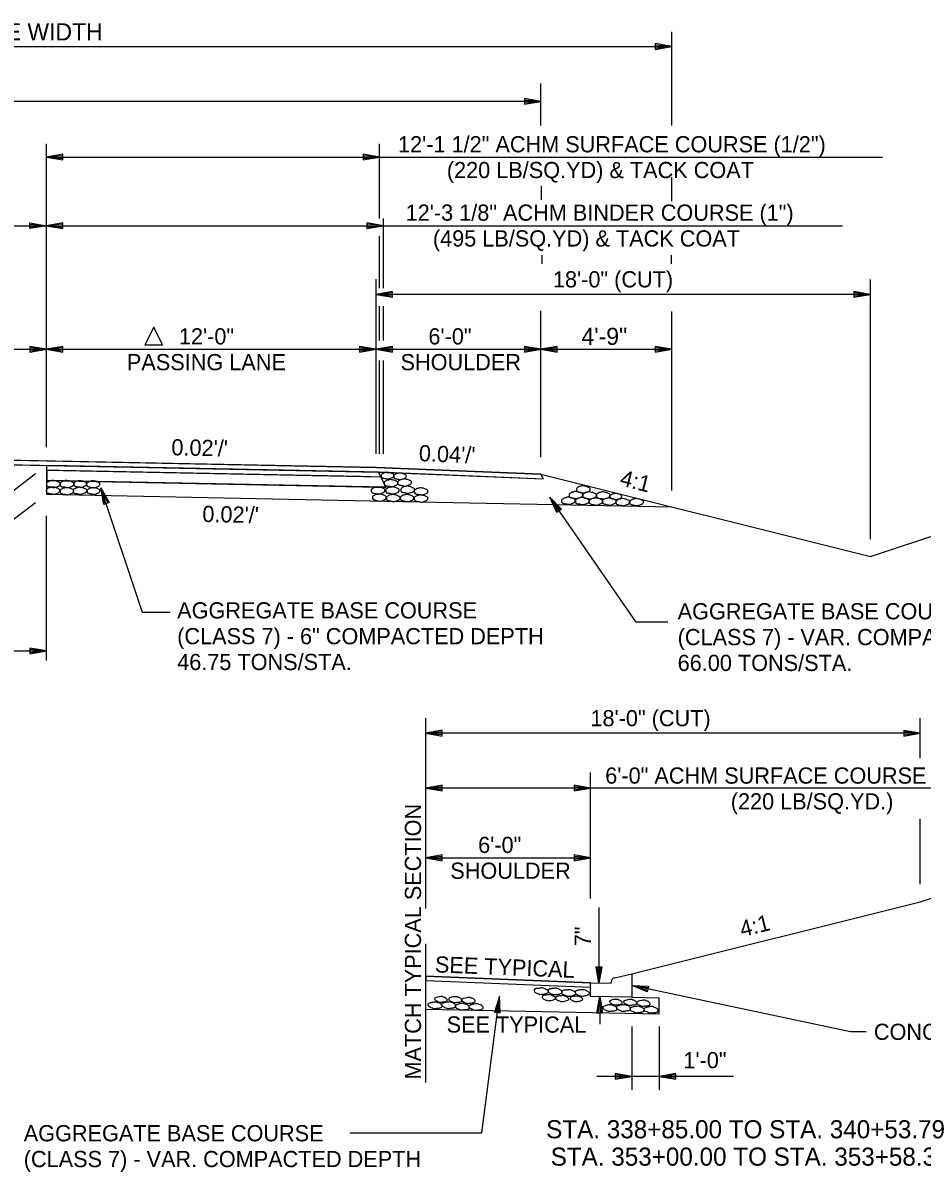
# Model space of a CAD drawing. Extents: x 1398183 to 1398373, y 1967240 to 1968889.
# Drawn here: x 1398256.3 to 1398289.03, y 1968479.69 to 1968521.54 of the extents above; entities that cross this region are included whole.
import ezdxf

# ---------------------------------------------------------------- set-up
doc = ezdxf.new("R2010")
doc.units = 0
for name, color, linetype in [('1', 7, 'Continuous'), ('10', 7, 'Continuous'), ('19', 7, 'Continuous'), ('42', 7, 'Continuous'), ('Level 1', 7, 'Continuous')]:
    doc.layers.add(name, color=color, linetype=linetype)

# ---------------------------------------------------------------- blocks, each defined once
blk = doc.blocks.new('ROCKS')
at = {"layer": '1'}
blk.add_spline([(0.013, 0.06), (0.053, 0.053), (0.107, 0.033), (0.133, 0.013), (0.133, -0.007), (0.12, -0.033), (0.107, -0.04), (0.073, -0.053), (0.033, -0.067), (0.013, -0.067), (-0.02, -0.06), (-0.06, -0.053), (-0.087, -0.047), (-0.113, -0.02), (-0.113, -0.007), (-0.107, 0.02), (-0.087, 0.033), (-0.067, 0.047), (-0.033, 0.053), (-0.02, 0.06), (0.013, 0.06)], degree=3, dxfattribs=at)

msp = doc.modelspace()

# ---------------------------------------------------------------- linework, layer by layer
at = {"layer": '10'}
msp.add_lwpolyline([(1398261.055, 1968510.466), (1398260.735, 1968509.824), (1398261.376, 1968509.824)], close=True, dxfattribs=at)
at = {"layer": '19'}
for p, q in [((1398279.917, 1968517.807), (1398279.917, 1968521.226)), ((1398222.545, 1968520.685), (1398279.917, 1968520.685)), ((1398279.317, 1968520.79), (1398279.317, 1968520.58)), ((1398279.917, 1968520.685), (1398279.317, 1968520.79)), ((1398279.757, 1968520.7), (1398279.317, 1968520.735)), ((1398279.317, 1968520.58), (1398279.917, 1968520.685)), ((1398279.317, 1968520.63), (1398279.757, 1968520.67)), ((1398275.152, 1968517.807), (1398275.152, 1968519.333)), ((1398275.152, 1968518.685), (1398225.119, 1968518.685)), ((1398274.552, 1968518.79), (1398274.552, 1968518.58)), ((1398275.152, 1968518.685), (1398274.552, 1968518.79)), ((1398274.992, 1968518.7), (1398274.552, 1968518.735)), ((1398274.552, 1968518.58), (1398275.152, 1968518.685)), ((1398274.552, 1968518.63), (1398274.992, 1968518.67)), ((1398257.15, 1968506.092), (1398257.15, 1968517.142)), ((1398269.279, 1968514.427), (1398269.279, 1968517.142)), ((1398257.75, 1968516.765), (1398257.15, 1968516.66)), ((1398257.15, 1968516.66), (1398257.75, 1968516.555)), ((1398257.15, 1968516.66), (1398287.584, 1968516.66)), ((1398257.75, 1968516.71), (1398257.31, 1968516.675)), ((1398257.31, 1968516.645), (1398257.75, 1968516.605)), ((1398257.75, 1968516.555), (1398257.75, 1968516.765)), ((1398268.679, 1968516.765), (1398268.679, 1968516.555)), ((1398269.279, 1968516.66), (1398268.679, 1968516.765)), ((1398269.119, 1968516.675), (1398268.679, 1968516.71)), ((1398268.679, 1968516.555), (1398269.279, 1968516.66)), ((1398268.679, 1968516.605), (1398269.119, 1968516.645)), ((1398279.911, 1968515.927), (1398279.911, 1968515.052)), ((1398275.17, 1968515.104), (1398275.17, 1968515.613)), ((1398269.417, 1968511.884), (1398269.417, 1968514.425)), ((1398233.15, 1968514.16), (1398286.13, 1968514.16)), ((1398256.55, 1968514.055), (1398256.55, 1968514.265)), ((1398256.55, 1968514.265), (1398257.15, 1968514.16)), ((1398256.55, 1968514.21), (1398256.99, 1968514.175)), ((1398257.15, 1968514.16), (1398256.55, 1968514.055)), ((1398256.99, 1968514.145), (1398256.55, 1968514.105)), ((1398257.75, 1968514.265), (1398257.15, 1968514.16)), ((1398257.15, 1968514.16), (1398257.75, 1968514.055)), ((1398257.75, 1968514.21), (1398257.31, 1968514.175)), ((1398257.31, 1968514.145), (1398257.75, 1968514.105)), ((1398257.75, 1968514.055), (1398257.75, 1968514.265)), ((1398268.817, 1968514.265), (1398268.817, 1968514.055)), ((1398269.417, 1968514.16), (1398268.817, 1968514.265)), ((1398269.257, 1968514.175), (1398268.817, 1968514.21)), ((1398268.817, 1968514.055), (1398269.417, 1968514.16)), ((1398268.817, 1968514.105), (1398269.257, 1968514.145)), ((1398269.279, 1968511.884), (1398269.279, 1968513.784)), ((1398275.204, 1968512.767), (1398275.204, 1968513.089)), ((1398279.911, 1968512.767), (1398279.911, 1968513.089)), ((1398269.15, 1968505.852), (1398269.15, 1968512.207)), ((1398287.15, 1968502.738), (1398287.15, 1968512.206)), ((1398269.75, 1968511.765), (1398269.15, 1968511.66)), ((1398285.15, 1968511.66), (1398269.15, 1968511.66)), ((1398269.15, 1968511.66), (1398269.75, 1968511.555)), ((1398287.15, 1968511.66), (1398269.15, 1968511.66)), ((1398269.75, 1968511.71), (1398269.31, 1968511.675)), ((1398269.31, 1968511.645), (1398269.75, 1968511.605)), ((1398269.75, 1968511.555), (1398269.75, 1968511.765)), ((1398286.55, 1968511.765), (1398286.55, 1968511.555)), ((1398287.15, 1968511.66), (1398286.55, 1968511.765)), ((1398286.99, 1968511.675), (1398286.55, 1968511.71)), ((1398286.55, 1968511.555), (1398287.15, 1968511.66)), ((1398286.55, 1968511.605), (1398286.99, 1968511.645)), ((1398269.279, 1968509.983), (1398269.279, 1968511.232)), ((1398269.417, 1968509.981), (1398269.417, 1968511.23)), ((1398275.15, 1968505.732), (1398275.15, 1968511.056)), ((1398279.916, 1968504.514), (1398279.916, 1968511.037)), ((1398256.55, 1968509.765), (1398256.55, 1968509.555)), ((1398257.15, 1968509.66), (1398256.55, 1968509.765)), ((1398257.75, 1968509.765), (1398257.15, 1968509.66)), ((1398257.75, 1968509.555), (1398257.75, 1968509.765)), ((1398268.55, 1968509.765), (1398268.55, 1968509.555)), ((1398269.15, 1968509.66), (1398268.55, 1968509.765)), ((1398269.75, 1968509.765), (1398269.15, 1968509.66)), ((1398269.75, 1968509.555), (1398269.75, 1968509.765)), ((1398274.55, 1968509.765), (1398274.55, 1968509.555)), ((1398275.15, 1968509.66), (1398274.55, 1968509.765)), ((1398275.75, 1968509.765), (1398275.15, 1968509.66)), ((1398275.75, 1968509.555), (1398275.75, 1968509.765)), ((1398279.317, 1968509.765), (1398279.317, 1968509.555)), ((1398279.917, 1968509.66), (1398279.317, 1968509.765)), ((1398245.15, 1968509.66), (1398257.15, 1968509.66)), ((1398256.99, 1968509.675), (1398256.55, 1968509.71)), ((1398256.55, 1968509.555), (1398257.15, 1968509.66)), ((1398256.55, 1968509.605), (1398256.99, 1968509.645)), ((1398257.15, 1968509.66), (1398257.75, 1968509.555)), ((1398257.15, 1968509.66), (1398269.15, 1968509.66)), ((1398257.75, 1968509.71), (1398257.31, 1968509.675)), ((1398257.31, 1968509.645), (1398257.75, 1968509.605)), ((1398268.99, 1968509.675), (1398268.55, 1968509.71)), ((1398268.55, 1968509.555), (1398269.15, 1968509.66)), ((1398268.55, 1968509.605), (1398268.99, 1968509.645)), ((1398269.15, 1968509.66), (1398275.15, 1968509.66)), ((1398269.15, 1968509.66), (1398269.75, 1968509.555)), ((1398269.75, 1968509.71), (1398269.31, 1968509.675)), ((1398269.31, 1968509.645), (1398269.75, 1968509.605)), ((1398274.99, 1968509.675), (1398274.55, 1968509.71)), ((1398274.55, 1968509.555), (1398275.15, 1968509.66)), ((1398274.55, 1968509.605), (1398274.99, 1968509.645)), ((1398275.15, 1968509.66), (1398279.916, 1968509.66)), ((1398275.15, 1968509.66), (1398275.75, 1968509.555)), ((1398275.75, 1968509.71), (1398275.31, 1968509.675)), ((1398275.31, 1968509.645), (1398275.75, 1968509.605)), ((1398279.757, 1968509.675), (1398279.317, 1968509.71)), ((1398279.317, 1968509.555), (1398279.917, 1968509.66)), ((1398279.317, 1968509.605), (1398279.757, 1968509.645)), ((1398269.279, 1968505.852), (1398269.279, 1968509.252)), ((1398269.417, 1968505.852), (1398269.417, 1968509.249)), ((1398257.15, 1968505.425), (1398257.15, 1968505.258)), ((1398257.15, 1968505.258), (1398257.15, 1968504.883)), ((1398257.15, 1968505.258), (1398269.322, 1968505.012)), ((1398268.585, 1968505.024), (1398257.611, 1968505.243)), ((1398269.237, 1968505.182), (1398269.322, 1968505.012)), ((1398287.15, 1968502.113), (1398296.517, 1968505.235)), ((1398256.753, 1968505.121), (1398254.051, 1968503.052)), ((1398257.15, 1968504.883), (1398257.15, 1968504.383)), ((1398269.511, 1968504.633), (1398257.15, 1968504.883)), ((1398269.328, 1968505.007), (1398268.585, 1968505.024)), ((1398269.322, 1968505.012), (1398269.511, 1968504.633)), ((1398269.518, 1968504.628), (1398269.328, 1968505.007)), ((1398275.15, 1968505.112), (1398287.15, 1968502.113)), ((1398275.15, 1968505.112), (1398275.235, 1968504.942)), ((1398259.233, 1968504.011), (1398259.132, 1968504.61)), ((1398259.132, 1968504.61), (1398259.43, 1968504.079)), ((1398260.643, 1968500.074), (1398259.133, 1968504.607)), ((1398259.28, 1968504.028), (1398259.17, 1968504.454)), ((1398259.196, 1968504.464), (1398259.379, 1968504.064)), ((1398268.662, 1968504.646), (1398269.518, 1968504.628)), ((1398256.747, 1968504.072), (1398254.065, 1968502.02)), ((1398259.43, 1968504.079), (1398259.233, 1968504.011)), ((1398278.623, 1968499.715), (1398275.478, 1968504.267)), ((1398275.731, 1968503.714), (1398275.478, 1968504.267)), ((1398275.478, 1968504.267), (1398275.904, 1968503.831)), ((1398275.771, 1968503.743), (1398275.555, 1968504.126)), ((1398275.578, 1968504.143), (1398275.858, 1968503.804)), ((1398257.15, 1968498.324), (1398257.15, 1968503.592)), ((1398275.904, 1968503.831), (1398275.731, 1968503.714)), ((1398261.656, 1968500.074), (1398260.643, 1968500.074)), ((1398279.774, 1968499.715), (1398278.623, 1968499.715)), ((1398233.15, 1968498.674), (1398257.15, 1968498.674)), ((1398256.55, 1968498.779), (1398256.55, 1968498.569)), ((1398257.15, 1968498.674), (1398256.55, 1968498.779)), ((1398256.99, 1968498.689), (1398256.55, 1968498.724)), ((1398256.55, 1968498.569), (1398257.15, 1968498.674)), ((1398256.55, 1968498.619), (1398256.99, 1968498.659)), ((1398270.961, 1968489.287), (1398270.961, 1968496.224)), ((1398288.961, 1968494.765), (1398288.961, 1968496.222)), ((1398271.561, 1968495.783), (1398270.961, 1968495.678)), ((1398288.961, 1968495.678), (1398270.961, 1968495.678)), ((1398270.961, 1968495.678), (1398271.561, 1968495.573)), ((1398271.561, 1968495.728), (1398271.121, 1968495.693)), ((1398271.121, 1968495.663), (1398271.561, 1968495.623)), ((1398271.561, 1968495.573), (1398271.561, 1968495.783)), ((1398288.361, 1968495.78), (1398288.361, 1968495.57)), ((1398288.961, 1968495.675), (1398288.361, 1968495.78)), ((1398288.801, 1968495.69), (1398288.361, 1968495.725)), ((1398288.361, 1968495.57), (1398288.961, 1968495.675)), ((1398288.361, 1968495.62), (1398288.801, 1968495.66)), ((1398276.961, 1968489.65), (1398276.961, 1968494.245)), ((1398271.561, 1968493.783), (1398270.961, 1968493.678)), ((1398294.328, 1968493.678), (1398270.961, 1968493.678)), ((1398270.961, 1968493.678), (1398271.561, 1968493.573)), ((1398271.561, 1968493.728), (1398271.121, 1968493.693)), ((1398271.121, 1968493.663), (1398271.561, 1968493.623)), ((1398271.561, 1968493.573), (1398271.561, 1968493.783)), ((1398276.361, 1968493.783), (1398276.361, 1968493.573)), ((1398276.961, 1968493.678), (1398276.361, 1968493.783)), ((1398276.801, 1968493.693), (1398276.361, 1968493.728)), ((1398276.361, 1968493.573), (1398276.961, 1968493.678)), ((1398276.361, 1968493.623), (1398276.801, 1968493.663)), ((1398288.961, 1968490.172), (1398288.961, 1968492.562)), ((1398288.961, 1968489.534), (1398294.559, 1968491.4)), ((1398271.561, 1968491.243), (1398270.961, 1968491.138)), ((1398270.961, 1968491.138), (1398276.961, 1968491.138)), ((1398270.961, 1968491.138), (1398271.561, 1968491.033)), ((1398271.561, 1968491.188), (1398271.121, 1968491.153)), ((1398271.121, 1968491.123), (1398271.561, 1968491.083)), ((1398271.561, 1968491.033), (1398271.561, 1968491.243)), ((1398276.361, 1968491.243), (1398276.361, 1968491.033)), ((1398276.961, 1968491.138), (1398276.361, 1968491.243)), ((1398276.801, 1968491.153), (1398276.361, 1968491.188)), ((1398276.361, 1968491.033), (1398276.961, 1968491.138)), ((1398276.361, 1968491.083), (1398276.801, 1968491.123)), ((1398277.266, 1968489.332), (1398277.266, 1968486.567)), ((1398278.461, 1968486.909), (1398288.961, 1968489.534)), ((1398270.961, 1968482.949), (1398270.961, 1968488.001)), ((1398277.161, 1968487.167), (1398277.371, 1968487.167)), ((1398277.266, 1968486.567), (1398277.161, 1968487.167)), ((1398277.251, 1968486.727), (1398277.211, 1968487.167)), ((1398277.371, 1968487.167), (1398277.266, 1968486.567)), ((1398277.316, 1968487.167), (1398277.281, 1968486.727)), ((1398277.841, 1968486.771), (1398278.461, 1968486.909)), ((1398278.461, 1968486.909), (1398278.461, 1968486.06)), ((1398276.961, 1968486.09), (1398276.961, 1968486.59)), ((1398276.961, 1968486.59), (1398277.711, 1968486.575)), ((1398277.711, 1968486.575), (1398277.711, 1968486.608)), ((1398286.421, 1968484.8), (1398278.461, 1968486.484)), ((1398279.025, 1968486.259), (1398278.461, 1968486.484)), ((1398278.461, 1968486.484), (1398279.069, 1968486.462)), ((1398279.034, 1968486.307), (1398278.613, 1968486.436)), ((1398278.619, 1968486.463), (1398279.055, 1968486.411)), ((1398279.069, 1968486.462), (1398279.025, 1968486.259)), ((1398273.006, 1968481.116), (1398273.643, 1968486.102)), ((1398273.643, 1968486.102), (1398273.464, 1968485.52)), ((1398273.611, 1968485.945), (1398273.517, 1968485.516)), ((1398273.622, 1968485.501), (1398273.639, 1968485.942)), ((1398273.671, 1968485.495), (1398273.643, 1968486.102)), ((1398278.461, 1968486.06), (1398276.961, 1968486.09)), ((1398277.189, 1968485.484), (1398277.294, 1968486.084)), ((1398277.239, 1968485.484), (1398277.279, 1968485.924)), ((1398277.294, 1968486.084), (1398277.399, 1968485.484)), ((1398277.294, 1968486.084), (1398277.294, 1968485.084)), ((1398277.309, 1968485.924), (1398277.344, 1968485.484)), ((1398279.461, 1968485.452), (1398279.461, 1968486.04)), ((1398273.464, 1968485.52), (1398273.671, 1968485.495)), ((1398277.399, 1968485.484), (1398277.189, 1968485.484)), ((1398278.461, 1968484.988), (1398278.461, 1968482.686)), ((1398279.461, 1968484.988), (1398279.461, 1968482.686)), ((1398286.991, 1968484.8), (1398286.421, 1968484.8)), ((1398282.166, 1968483.178), (1398277.185, 1968483.178)), ((1398277.861, 1968483.283), (1398277.861, 1968483.073)), ((1398278.461, 1968483.178), (1398277.861, 1968483.283)), ((1398278.301, 1968483.193), (1398277.861, 1968483.228)), ((1398277.861, 1968483.073), (1398278.461, 1968483.178)), ((1398277.861, 1968483.123), (1398278.301, 1968483.163)), ((1398280.061, 1968483.283), (1398279.461, 1968483.178)), ((1398279.461, 1968483.178), (1398280.061, 1968483.073)), ((1398280.061, 1968483.228), (1398279.621, 1968483.193)), ((1398279.621, 1968483.163), (1398280.061, 1968483.123)), ((1398280.061, 1968483.073), (1398280.061, 1968483.283)), ((1398268.208, 1968481.116), (1398273.006, 1968481.116))]:
    msp.add_line(p, q, dxfattribs=at)
for points in [[(1398225.065, 1968505.102), (1398233.065, 1968505.422), (1398245.15, 1968505.666), (1398269.252, 1968505.191), (1398275.237, 1968504.942), (1398275.15, 1968505.112), (1398269.152, 1968505.352), (1398245.15, 1968505.832), (1398233.15, 1968505.592), (1398225.15, 1968505.272)], [(1398257.15, 1968505.425), (1398257.15, 1968505.258), (1398257.959, 1968505.242), (1398266.824, 1968505.062), (1398269.321, 1968505.011), (1398269.236, 1968505.181), (1398268.177, 1968505.203), (1398257.894, 1968505.41)], [(1398270.961, 1968486.664), (1398276.961, 1968486.424), (1398276.961, 1968486.59), (1398270.961, 1968486.83)]]:
    msp.add_lwpolyline(points, close=True, dxfattribs=at)
for points in [[(1398225.065, 1968505.102), (1398233.065, 1968505.422), (1398245.15, 1968505.666), (1398269.237, 1968505.182), (1398275.235, 1968504.942)], [(1398245.15, 1968505.832), (1398257.15, 1968505.592), (1398269.15, 1968505.352), (1398275.15, 1968505.112)], [(1398257.611, 1968505.243), (1398257.158, 1968505.254), (1398257.158, 1968504.879)], [(1398257.158, 1968504.879), (1398257.738, 1968504.865), (1398268.662, 1968504.646)], [(1398257.15, 1968504.383), (1398269.511, 1968504.133), (1398279.907, 1968503.923)], [(1398270.961, 1968486.83), (1398276.961, 1968486.59)], [(1398270.961, 1968486.664), (1398276.961, 1968486.424)], [(1398278.461, 1968486.06), (1398279.461, 1968486.04)], [(1398270.961, 1968485.622), (1398279.461, 1968485.452)]]:
    msp.add_lwpolyline(points, dxfattribs=at)
msp.add_arc((1398277.877, 1968486.608), 0.167, 102.5288, 180, dxfattribs=at)
at = {"layer": '42'}
msp.add_lwpolyline([(1398245.15, 1968505.666), (1398257.15, 1968505.425)], dxfattribs=at)

# ---------------------------------------------------------------- block references
at = {"layer": 'Level 1'}
for p, xscale, yscale, rotation in [((1398269.549, 1968505.062), 1.8771740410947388, 1.8771740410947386, -0.173618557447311), ((1398270.006, 1968505.037), 1.849824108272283, 1.8498241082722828, -0.17361855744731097), ((1398257.376, 1968504.758), 2.011654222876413, 2.0116542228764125, -0.17361855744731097), ((1398257.875, 1968504.756), 2.011654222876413, 2.0116542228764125, -0.17361855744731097), ((1398258.357, 1968504.759), 1.907051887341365, 1.9070518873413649, -0.173618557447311), ((1398258.833, 1968504.747), 1.9598639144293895, 1.959863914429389, -0.173618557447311), ((1398269.67, 1968504.788), 2.011654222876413, 2.0116542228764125, -0.17361855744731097), ((1398270.169, 1968504.813), 2.011654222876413, 2.0116542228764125, -0.17361855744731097), ((1398257.368, 1968504.517), 2.011654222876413, 2.0116542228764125, -0.17361855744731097), ((1398257.872, 1968504.498), 2.011654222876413, 2.0116542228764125, -0.17361855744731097), ((1398258.347, 1968504.512), 1.9974694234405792, 1.9974694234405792, -0.17361855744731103), ((1398258.844, 1968504.503), 1.890205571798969, 1.8902055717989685, -0.17361855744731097), ((1398269.2, 1968504.522), 2.011654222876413, 2.0116542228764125, -0.17361855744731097), ((1398269.251, 1968504.264), 2.011654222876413, 2.0116542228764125, -0.17361855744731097), ((1398269.724, 1968504.527), 2.011654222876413, 2.0116542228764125, -0.17361855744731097), ((1398269.755, 1968504.246), 2.011654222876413, 2.0116542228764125, -0.17361855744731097), ((1398270.26, 1968504.249), 2.011654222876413, 2.0116542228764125, -0.17361855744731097), ((1398270.279, 1968504.55), 2.011654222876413, 2.0116542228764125, -0.17361855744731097), ((1398270.764, 1968504.231), 2.011654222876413, 2.0116542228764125, -0.17361855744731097), ((1398270.768, 1968504.489), 2.011654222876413, 2.0116542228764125, -0.17361855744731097), ((1398276.404, 1968504.354), 2.011654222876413, 2.0116542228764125, -0.17361855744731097), ((1398276.673, 1968504.562), 2.011654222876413, 2.0116542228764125, -0.17361855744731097), ((1398276.904, 1968504.342), 2.011654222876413, 2.0116542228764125, -0.17361855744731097), ((1398277.399, 1968504.342), 2.011654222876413, 2.0116542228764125, -0.17361855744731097), ((1398277.861, 1968504.303), 1.7335100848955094, 1.7335100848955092, -0.173618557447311), ((1398276.133, 1968504.147), 2.011654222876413, 2.0116542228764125, -0.17361855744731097), ((1398276.133, 1968504.147), 2.011654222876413, 2.0116542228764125, -0.17361855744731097), ((1398276.638, 1968504.137), 2.011654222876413, 2.0116542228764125, -0.17361855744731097), ((1398276.638, 1968504.137), 2.011654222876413, 2.0116542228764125, -0.17361855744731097), ((1398277.13, 1968504.119), 2.011654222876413, 2.0116542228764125, -0.17361855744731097), ((1398277.13, 1968504.119), 2.011654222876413, 2.0116542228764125, -0.17361855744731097), ((1398277.62, 1968504.119), 2.011654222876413, 2.0116542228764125, -0.17361855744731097), ((1398277.62, 1968504.119), 2.011654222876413, 2.0116542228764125, -0.17361855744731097), ((1398278.113, 1968504.099), 2.011654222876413, 2.0116542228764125, -0.17361855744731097), ((1398278.113, 1968504.099), 2.011654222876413, 2.0116542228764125, -0.17361855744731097), ((1398278.616, 1968504.099), 2.011654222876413, 2.0116542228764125, -0.17361855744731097), ((1398278.616, 1968504.099), 2.011654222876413, 2.0116542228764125, -0.17361855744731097), ((1398275.145, 1968486.277), 2.0116542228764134, -2.011654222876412, -4.336484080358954), ((1398275.65, 1968486.266), 2.0116542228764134, -2.011654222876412, -4.336484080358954), ((1398276.144, 1968486.211), 2.0116542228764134, -2.011654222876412, -4.336484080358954), ((1398276.642, 1968486.214), 2.0116542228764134, -2.011654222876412, -4.336484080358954), ((1398271.317, 1968485.771), 2.0116542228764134, -2.011654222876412, 175.66351591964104), ((1398271.531, 1968485.985), 1.773922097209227, -1.7739220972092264, 175.66351591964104), ((1398271.815, 1968485.774), 2.0116542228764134, -2.011654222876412, 175.66351591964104), ((1398272.053, 1968485.977), 1.851115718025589, -1.8511157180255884, 175.66351591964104), ((1398272.535, 1968485.947), 1.8866375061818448, -1.886637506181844, 175.66351591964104), ((1398275.424, 1968486.038), 1.8866375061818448, -1.886637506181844, -4.336484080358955), ((1398275.906, 1968486.008), 1.851115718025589, -1.8511157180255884, -4.336484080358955), ((1398276.427, 1968486), 1.773922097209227, -1.7739220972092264, -4.336484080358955), ((1398277.899, 1968485.884), 1.773922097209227, -1.7739220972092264, 175.66351591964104), ((1398278.421, 1968485.877), 1.851115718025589, -1.8511157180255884, 175.66351591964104), ((1398278.903, 1968485.846), 1.8866375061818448, -1.886637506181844, 175.66351591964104), ((1398272.309, 1968485.719), 2.0116542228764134, -2.011654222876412, 175.66351591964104), ((1398272.814, 1968485.708), 2.0116542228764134, -2.011654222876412, 175.66351591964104), ((1398277.685, 1968485.67), 2.0116542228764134, -2.011654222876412, 175.66351591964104), ((1398278.182, 1968485.674), 2.0116542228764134, -2.011654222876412, 175.66351591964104), ((1398278.677, 1968485.618), 2.0116542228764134, -2.011654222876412, 175.66351591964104), ((1398279.182, 1968485.607), 2.0116542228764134, -2.011654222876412, 175.66351591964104)]:
    msp.add_blockref('ROCKS', p, dxfattribs=dict(at, xscale=xscale, yscale=yscale, rotation=rotation))

# ---------------------------------------------------------------- texts
at = {"layer": '10'}
for s, height, p in [('18\'-0" (CUT)', 0.59001, (1398275.59, 1968511.912)), ('12\'-0"', 0.59, (1398261.972, 1968509.835)), ('6\'-0"', 0.59, (1398271.056, 1968509.835)), ('PASSING LANE', 0.59001, (1398260.079, 1968508.895)), ('SHOULDER', 0.59, (1398270.043, 1968508.895)), ('18\'-0" (CUT)', 0.59001, (1398276.956, 1968495.929)), ('6\'-0" ACHM SURFACE COURSE (1/2")', 0.59001, (1398277.494, 1968493.839)), ('(220 LB/SQ.YD.)', 0.59001, (1398282.065, 1968492.899)), ('6\'-0"', 0.59, (1398272.867, 1968491.313)), ('SHOULDER', 0.59, (1398271.854, 1968490.373)), ('1\'-0"', 0.59, (1398280.34, 1968483.473))]:
    msp.add_text(s, height=height, dxfattribs=at).set_placement(p)
for s, height, rotation, p in [("0.04'/'", 0.59, 357.7094, (1398270.7, 1968505.586)), ('4:1', 0.59, 345.9638, (1398277.997, 1968504.705)), ('MATCH TYPICAL SECTION', 0.59001, 90, (1398270.789, 1968483.062)), ('4:1', 0.59, 14.0362, (1398282.479, 1968488.245)), ('SEE TYPICAL', 0.59001, 357.7094, (1398271.285, 1968486.967)), ('SEE TYPICAL', 0.59001, 359.948, (1398271.719, 1968484.773))]:
    msp.add_text(s, height=height, rotation=rotation, dxfattribs=at).set_placement(p)
at = {"layer": '19'}
for s, height, p in [('57\'-3" SUBGRADE WIDTH', 0.625, (1398249.173, 1968520.909)), ('4\'-9"', 0.625, (1398276.63, 1968509.818)), ('CONC. COMB. C&G (TYPE B-1) (1\'-6")', 0.59001, (1398287.276, 1968484.505)), ('STA. 338+85.00 TO STA. 340+53.79', 0.65999, (1398275.344, 1968480.922)), ('STA. 353+00.00 TO STA. 353+58.31', 0.65999, (1398275.508, 1968479.925))]:
    msp.add_text(s, height=height, dxfattribs=at).set_placement(p)
for s, height, rotation, p in [("0.02'/'", 0.59, 358.7305, (1398261.694, 1968505.8)), ("0.02'/'", 0.59, 358.7305, (1398262.821, 1968503.372)), ('AGGREGATE BASE COURSE', 0.59001, 360, (1398261.91, 1968499.855)), ('AGGREGATE BASE COURSE', 0.59001, 360, (1398280.132, 1968499.822)), ('(CLASS 7) - 6" COMPACTED DEPTH', 0.59001, 360, (1398261.91, 1968498.915)), ('(CLASS 7) - VAR. COMPACTED DEPTH', 0.59001, 360, (1398280.132, 1968498.882)), ('46.75 TONS/STA.', 0.59001, 360, (1398261.91, 1968497.975)), ('66.00 TONS/STA.', 0.59001, 360, (1398280.132, 1968497.942)), ('AGGREGATE BASE COURSE', 0.59001, 360, (1398256.323, 1968480.812)), ('(CLASS 7) - VAR. COMPACTED DEPTH', 0.59001, 360, (1398256.323, 1968479.872))]:
    msp.add_text(s, height=height, rotation=rotation, dxfattribs=at).set_placement(p)
at = {"layer": '42'}
for s, height, rotation, p in [('12\'-1 1/2" ACHM SURFACE COURSE (1/2")', 0.59001, 360, (1398269.951, 1968516.832)), ('(220 LB/SQ.YD) & TACK COAT', 0.59001, 360, (1398271.728, 1968515.892)), ('12\'-3 1/8" ACHM BINDER COURSE (1")', 0.59001, 360, (1398270.228, 1968514.341)), ('(495 LB/SQ.YD) & TACK COAT', 0.59001, 360, (1398271.22, 1968513.401)), ('7"', 0.59, 90, (1398276.974, 1968487.917))]:
    msp.add_text(s, height=height, rotation=rotation, dxfattribs=at).set_placement(p)

doc.saveas('drawing.dxf')
